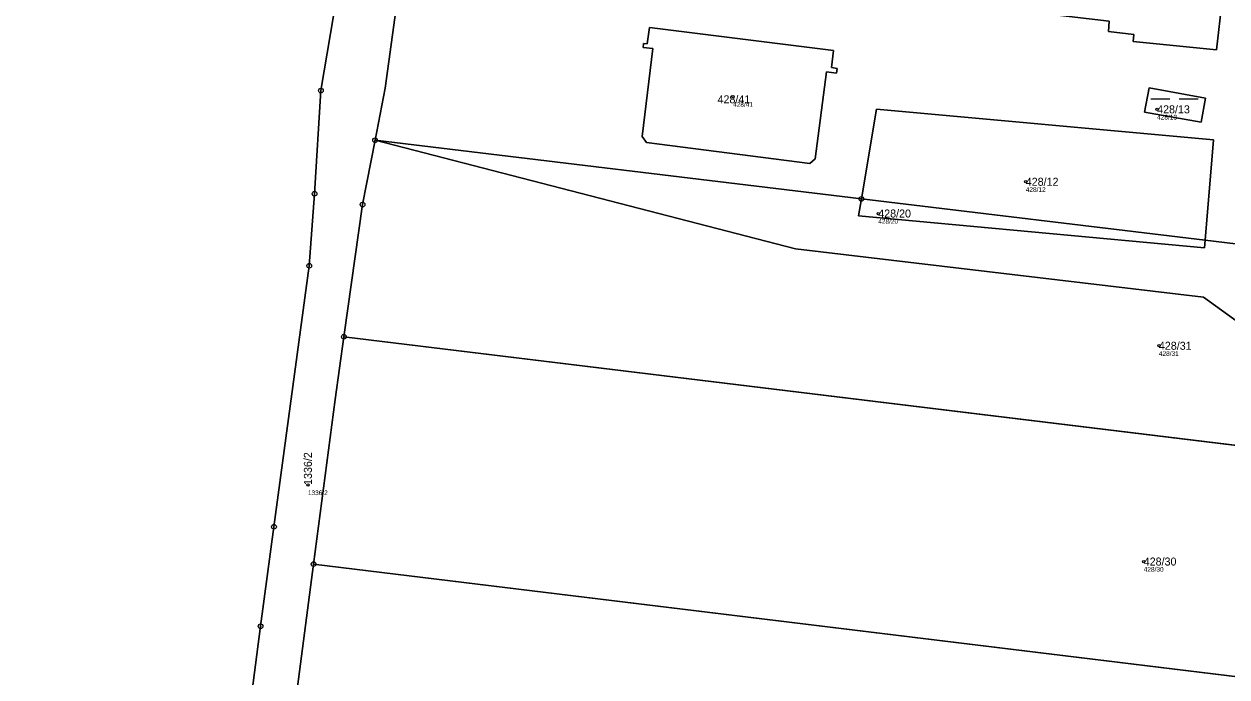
# Model space of a CAD drawing. Extents: x -658203 to -653176, y -1156738 to -1151709.
# Drawn here: x -654931.6 to -654676.1, y -1154980.1 to -1154841.5 of the extents above; entities that cross this region are included whole.
import ezdxf

# ---------------------------------------------------------------- set-up
doc = ezdxf.new("R2010")
doc.units = 0
for name, color, linetype in [('Vrstva 1', 7, 'Continuous'), ('Vrstva 2', 7, 'Continuous'), ('Vrstva 3', 7, 'Continuous'), ('Vrstva 50', 7, 'Continuous'), ('Vrstva 51', 7, 'Continuous'), ('Vrstva 52', 7, 'Continuous'), ('Vrstva 8', 7, 'Continuous')]:
    doc.layers.add(name, color=color, linetype=linetype)

msp = doc.modelspace()

# ---------------------------------------------------------------- linework, layer by layer
at = {"layer": 'Vrstva 1'}
for p, q in [((-654753.79, -1154878.61), (-654857.07, -1154866.18)), ((-654753.79, -1154878.61), (-654680.78, -1154887.4)), ((-654646.28, -1154891.55), (-654680.78, -1154887.4)), ((-654545.58, -1154946.59), (-654863.68, -1154907.88)), ((-654870.11, -1154956.13), (-654521.15, -1154998.7))]:
    msp.add_line(p, q, dxfattribs=at)
for points in [[(-654859.14, -1154779.42), (-654863.83, -1154827.61), (-654868.57, -1154855.63), (-654869.92, -1154877.53), (-654871.04, -1154892.81), (-654878.53, -1154948.22), (-654881.38, -1154969.33), (-654888.19, -1155021.77), (-654893.27, -1155058.51)], [(-654857.07, -1154866.18), (-654854.91, -1154855.13), (-654851.29, -1154828.79), (-654849.63, -1154815.54)], [(-654677.14, -1154836.51), (-654678.36, -1154847), (-654696.07, -1154845.2), (-654695.89, -1154843.7), (-654701.33, -1154843.07), (-654701.15, -1154840.88), (-654723.6, -1154838.26), (-654721.87, -1154822.89)], [(-654763.57, -1154870.09), (-654764.74, -1154871.08), (-654799.43, -1154866.67), (-654800.37, -1154865.38), (-654798.06, -1154846.68), (-654800.12, -1154846.48), (-654800.04, -1154845.63), (-654799.29, -1154845.71), (-654798.81, -1154842.24), (-654759.73, -1154847.11), (-654760.1, -1154850.72), (-654758.9, -1154850.93), (-654759.07, -1154851.94), (-654761.21, -1154851.63), (-654763.57, -1154870.09)], [(-654680.71, -1154857.22), (-654692.64, -1154855.05), (-654693.63, -1154860.19), (-654681.63, -1154862.33), (-654680.71, -1154857.22)], [(-654680.78, -1154887.4), (-654678.99, -1154866.06), (-654750.59, -1154859.55), (-654753.79, -1154878.61)], [(-654857.07, -1154866.18), (-654859.73, -1154879.82), (-654863.68, -1154907.88)], [(-654857.07, -1154866.18), (-654767.78, -1154889.24), (-654681.09, -1154899.44), (-654665.84, -1154910.51), (-654639.37, -1154915.2), (-654599.27, -1154915.03), (-654562.58, -1154920.06), (-654545.58, -1154946.59)], [(-654680.78, -1154887.4), (-654680.91, -1154888.98), (-654754.4, -1154882.22), (-654753.79, -1154878.61)], [(-654863.68, -1154907.88), (-654865.55, -1154921.21), (-654870.11, -1154956.13)], [(-654875.09, -1154995.99), (-654873.94, -1154985.45), (-654870.11, -1154956.13)]]:
    msp.add_lwpolyline(points, dxfattribs=at)
at = {"layer": 'Vrstva 3'}
for p, q in [((-654692.29, -1154857.37), (-654688.27, -1154857.37)), ((-654686.26, -1154857.37), (-654682.24, -1154857.37))]:
    msp.add_line(p, q, dxfattribs=at)
at = {"layer": 'Vrstva 50'}
for centre in [(-654781.03, -1154856.91), (-654690.97, -1154859.61), (-654718.87, -1154874.98), (-654750.2, -1154881.72), (-654690.6, -1154909.79), (-654871.33, -1154939.33), (-654693.82, -1154955.59)]:
    msp.add_circle(centre, 0.25, dxfattribs=at)
at = {"layer": 'Vrstva 51'}
for points in [[(-654873.94, -1154985.45), (-654870.11, -1154956.13), (-654865.55, -1154921.21), (-654863.68, -1154907.88), (-654859.73, -1154879.82), (-654857.07, -1154866.18), (-654854.91, -1154855.13), (-654851.29, -1154828.79), (-654849.63, -1154815.54), (-654846.53, -1154790.82), (-654845.16, -1154779.84), (-654844.24, -1154771.39), (-654841.89, -1154749.68), (-654840.22, -1154734.23), (-654833.63, -1154691.48)], [(-654849.08, -1154708.5), (-654849.83, -1154713.85), (-654852.88, -1154735.44), (-654855.11, -1154751.18), (-654858.04, -1154771.96), (-654858.74, -1154776.91), (-654859.14, -1154779.42), (-654863.83, -1154827.61), (-654868.57, -1154855.63), (-654869.92, -1154877.53), (-654871.04, -1154892.81), (-654878.53, -1154948.22), (-654881.38, -1154969.33), (-654888.19, -1155021.77)], [(-654888.19, -1155021.77), (-654881.38, -1154969.33), (-654878.53, -1154948.22), (-654871.04, -1154892.81), (-654869.92, -1154877.53), (-654868.57, -1154855.63), (-654863.83, -1154827.61), (-654859.14, -1154779.42), (-654948.92, -1154780), (-655031.82, -1154781.11), (-655024.99, -1154861.69), (-655026.87, -1154868.21), (-655027.87, -1154871.15), (-655031.7, -1154876.1), (-655101.79, -1154948.87), (-655121.89, -1154969.75), (-655133.12, -1154981.41)], [(-654851.29, -1154828.79), (-654854.91, -1154855.13), (-654857.07, -1154866.18), (-654753.79, -1154878.61), (-654750.59, -1154859.55), (-654678.99, -1154866.06), (-654680.78, -1154887.4), (-654646.28, -1154891.55)], [(-654677.14, -1154836.51), (-654678.36, -1154847), (-654696.07, -1154845.2), (-654695.89, -1154843.7), (-654701.33, -1154843.07), (-654701.15, -1154840.88)]]:
    msp.add_lwpolyline(points, dxfattribs=at)
for points in [[(-654699.39, -1154827.57), (-654699.16, -1154825.55), (-654721.87, -1154822.89), (-654723.6, -1154838.26), (-654701.15, -1154840.88), (-654701.33, -1154843.07), (-654695.89, -1154843.7), (-654696.07, -1154845.2), (-654678.36, -1154847), (-654677.14, -1154836.51), (-654676.22, -1154828.62), (-654693.87, -1154826.56), (-654694.18, -1154828.14)], [(-654763.57, -1154870.09), (-654761.21, -1154851.63), (-654759.07, -1154851.94), (-654758.9, -1154850.93), (-654760.1, -1154850.72), (-654759.73, -1154847.11), (-654798.81, -1154842.24), (-654799.29, -1154845.71), (-654800.04, -1154845.63), (-654800.12, -1154846.48), (-654798.06, -1154846.68), (-654800.37, -1154865.38), (-654799.43, -1154866.67), (-654764.74, -1154871.08)], [(-654763.57, -1154870.09), (-654764.74, -1154871.08), (-654799.43, -1154866.67), (-654800.37, -1154865.38), (-654798.06, -1154846.68), (-654800.12, -1154846.48), (-654800.04, -1154845.63), (-654799.29, -1154845.71), (-654798.81, -1154842.24), (-654759.73, -1154847.11), (-654760.1, -1154850.72), (-654758.9, -1154850.93), (-654759.07, -1154851.94), (-654761.21, -1154851.63)], [(-654680.71, -1154857.22), (-654681.63, -1154862.33), (-654693.63, -1154860.19), (-654692.64, -1154855.05)], [(-654680.71, -1154857.22), (-654692.64, -1154855.05), (-654693.63, -1154860.19), (-654681.63, -1154862.33)], [(-654680.78, -1154887.4), (-654678.99, -1154866.06), (-654750.59, -1154859.55), (-654753.79, -1154878.61)], [(-654863.68, -1154907.88), (-654545.58, -1154946.59), (-654562.58, -1154920.06), (-654599.27, -1154915.03), (-654639.37, -1154915.2), (-654665.84, -1154910.51), (-654681.09, -1154899.44), (-654767.78, -1154889.24), (-654857.07, -1154866.18), (-654859.73, -1154879.82)], [(-654646.32, -1154891.99), (-654646.28, -1154891.55), (-654680.78, -1154887.4), (-654680.91, -1154888.98), (-654754.4, -1154882.22), (-654753.79, -1154878.61), (-654857.07, -1154866.18), (-654767.78, -1154889.24), (-654681.09, -1154899.44), (-654665.84, -1154910.51), (-654639.37, -1154915.2), (-654599.27, -1154915.03), (-654562.58, -1154920.06), (-654545.58, -1154946.59), (-654519.62, -1154949.75), (-654518.55, -1154906.93), (-654613.68, -1154895.48), (-654627.64, -1154893.64), (-654632.52, -1154893.21)], [(-654753.79, -1154878.61), (-654754.4, -1154882.22), (-654680.91, -1154888.98), (-654680.78, -1154887.4)], [(-654520.68, -1154985.44), (-654545.58, -1154946.59), (-654863.68, -1154907.88), (-654865.55, -1154921.21), (-654870.11, -1154956.13), (-654521.15, -1154998.7)], [(-654521.15, -1154998.7), (-654870.11, -1154956.13), (-654873.94, -1154985.45), (-654875.09, -1154995.99), (-654520.24, -1155039.22), (-654521.54, -1155009.67)]]:
    msp.add_lwpolyline(points, close=True, dxfattribs=at)
at = {"layer": 'Vrstva 52'}
msp.add_lwpolyline([(-654696.07, -1154845.2), (-654678.36, -1154847), (-654677.14, -1154836.51), (-654676.22, -1154828.62), (-654693.87, -1154826.56), (-654694.18, -1154828.14), (-654699.39, -1154827.57), (-654699.16, -1154825.55), (-654721.87, -1154822.89), (-654723.6, -1154838.26), (-654701.15, -1154840.88), (-654701.33, -1154843.07), (-654695.89, -1154843.7)], close=True, dxfattribs=at)
at = {"layer": 'Vrstva 8'}
for centre, radius in [((-654868.57, -1154855.63), 0.5), ((-654868.57, -1154855.63), 0.0303), ((-654857.07, -1154866.18), 0.5), ((-654857.07, -1154866.18), 0.0303), ((-654869.92, -1154877.53), 0.5), ((-654869.92, -1154877.53), 0.0303), ((-654859.73, -1154879.82), 0.5), ((-654859.73, -1154879.82), 0.0303), ((-654753.79, -1154878.61), 0.5), ((-654753.79, -1154878.61), 0.0303), ((-654871.04, -1154892.81), 0.5), ((-654871.04, -1154892.81), 0.0303), ((-654863.68, -1154907.88), 0.5), ((-654863.68, -1154907.88), 0.0303), ((-654878.53, -1154948.22), 0.5), ((-654878.53, -1154948.22), 0.0303), ((-654870.11, -1154956.13), 0.5), ((-654870.11, -1154956.13), 0.0303), ((-654881.38, -1154969.33), 0.5), ((-654881.38, -1154969.33), 0.0303)]:
    msp.add_circle(centre, radius, dxfattribs=at)

# ---------------------------------------------------------------- texts
at = {"layer": 'Vrstva 2'}
for s, p in [('428/41', (-654784.33, -1154858.33)), ('428/13', (-654690.97, -1154860.46)), ('428/12', (-654718.87, -1154875.83)), ('428/20', (-654750.2, -1154882.57)), ('428/31', (-654690.6, -1154910.64)), ('428/30', (-654693.82, -1154956.44))]:
    msp.add_text(s, height=1.7, dxfattribs=at).set_placement(p)
msp.add_text('1336/2', height=1.7, rotation=90, dxfattribs=at).set_placement((-654870.48, -1154939.33))
at = {"layer": 'Vrstva 50'}
for s, p in [('428/41', (-654781.03, -1154859.07)), ('428/13', (-654690.97, -1154861.77)), ('428/12', (-654718.87, -1154877.14)), ('428/20', (-654750.2, -1154883.88)), ('428/31', (-654690.6, -1154911.95)), ('1336/2', (-654871.33, -1154941.49)), ('428/30', (-654693.82, -1154957.75))]:
    msp.add_text(s, height=1, dxfattribs=at).set_placement(p)

doc.saveas('drawing.dxf')
